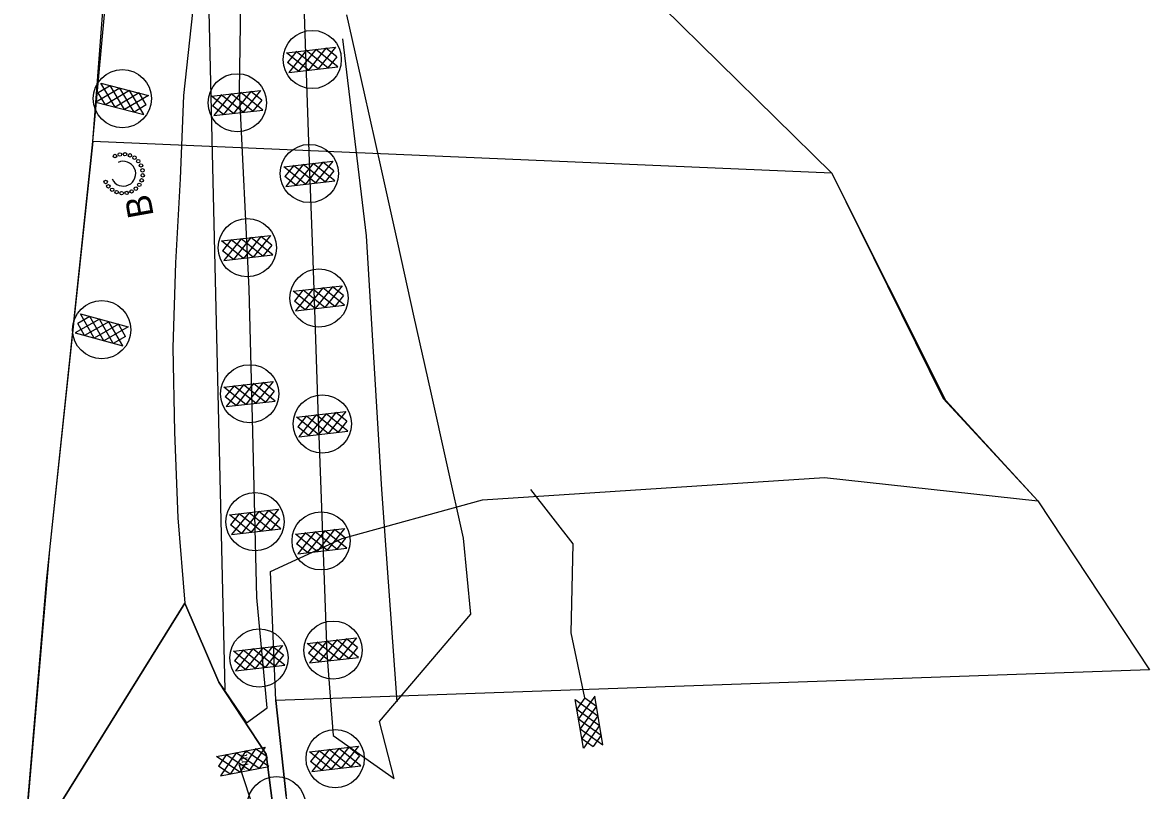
# Model space of a CAD drawing. Extents: x 400935 to 481562, y 415700 to 505362.
# Drawn here: x 474468 to 475127, y 503837 to 504287 of the extents above; entities that cross this region are included whole.
import ezdxf

# ---------------------------------------------------------------- set-up
doc = ezdxf.new("R2010")
doc.units = 0
for name, color, linetype in [('Excelsior Wattle Line Style Final', 7, 'Continuous'), ('Label B CG CELL', 7, 'Continuous'), ('Matting on Slope Note Final CELL', 7, 'Continuous'), ('Old_Level_2', 7, 'Continuous'), ('Rock Pipe Inlet Sediment Trap Type B CG CELL', 7, 'Continuous'), ('Rock Silt Check Type A Both CELL', 7, 'Continuous'), ('Rock Silt Check Type A with Matting and PAM CG CELL', 7, 'Continuous'), ('Rock Silt Check Type A with Matting and PAM Final CELL', 7, 'Continuous'), ('Scratch_Level_3', 7, 'Continuous'), ('Scratch_Level_4', 7, 'Continuous'), ('Temporary Silt Fence Both', 7, 'Continuous')]:
    doc.layers.add(name, color=color, linetype=linetype)

msp = doc.modelspace()

# ---------------------------------------------------------------- linework, layer by layer
at = {"layer": 'Excelsior Wattle Line Style Final'}
msp.add_line((474585.99, 503896.08), (474576.05, 504322.62), dxfattribs=at)
msp.add_lwpolyline([(474686.79, 503889.03), (474677.68, 504013.42), (474668.88, 504161.85), (474654.91, 504277.09), (474654.91, 504277.09)], dxfattribs=at)
at = {"layer": 'Matting on Slope Note Final CELL'}
for p, q in [((474566.88, 504292.53), (474561.67, 504243.99)), ((474667.4, 504246.2), (474657.37, 504291.29)), ((474677.28, 504201.74), (474667.4, 504246.2)), ((474561.67, 504243.99), (474559.66, 504195.21)), ((474687.06, 504157.79), (474677.28, 504201.74)), ((474559.66, 504195.21), (474557.11, 504146.05)), ((474696.75, 504114.22), (474687.06, 504157.79)), ((474557.11, 504146.05), (474555.48, 504096.51)), ((474706.38, 504070.94), (474696.75, 504114.22)), ((474555.48, 504096.51), (474556.49, 504046.86)), ((474715.96, 504027.84), (474706.38, 504070.94)), ((474556.49, 504046.86), (474558.32, 503996.88)), ((474725.53, 503984.81), (474715.96, 504027.84)), ((474558.32, 503996.88), (474562.43, 503946.88)), ((474729.84, 503940.34), (474725.53, 503984.81)), ((474562.43, 503946.88), (474582.45, 503900.64)), ((474676.32, 503877.58), (474729.84, 503940.34)), ((474582.45, 503900.64), (474598.56, 503876.71)), ((474684.93, 503844.28), (474676.32, 503877.58))]:
    msp.add_line(p, q, dxfattribs=at)
for points in [[(474598.56, 503876.71), (474610.64, 503885.55), (474604.64, 503950.12), (474602.2, 504047.14), (474600.1, 504130.89), (474594.49, 504246.69), (474595.54, 504324.66), (474597.97, 504383.09), (474599.37, 504430.72), (474607.08, 504475.48), (474609.67, 504494.69), (474611.07, 504546.92), (474616.75, 504589.94)], [(474686.28, 504550.27), (474667.85, 504549.83), (474651.57, 504492.73), (474646.89, 504443.04), (474642.05, 504389.56), (474642.05, 504389.56), (474631.32, 504337.88), (474632.23, 504291.63), (474633.85, 504245.5), (474635.48, 504199.42), (474637.11, 504153.27), (474638.75, 504106.95), (474640.4, 504060.34), (474642.06, 504013.33), (474643.74, 503965.79), (474645.55, 503917.63), (474649.31, 503869.29), (474684.93, 503844.28)]]:
    msp.add_lwpolyline(points, dxfattribs=at)
at = {"layer": 'Old_Level_2'}
for p, q in [((474581.1, 503857.05), (474609.46, 503862.6)), ((474609.46, 503862.6), (474600.34, 503849.05)), ((474594.65, 503847.93), (474581.1, 503857.05)), ((474586.7, 503858.1), (474582.19, 503851.41)), ((474592.43, 503859.27), (474583.31, 503845.72)), ((474600.34, 503849.05), (474586.74, 503858.15)), ((474598.12, 503860.38), (474588.96, 503846.82)), ((474605.98, 503850.15), (474592.43, 503859.27)), ((474603.76, 503861.5), (474594.65, 503847.93)), ((474611.68, 503851.26), (474598.12, 503860.38)), ((474610.58, 503856.96), (474603.76, 503861.5)), ((474610.58, 503856.96), (474605.98, 503850.15)), ((474588.96, 503846.82), (474582.19, 503851.41)), ((474583.31, 503845.72), (474611.68, 503851.26))]:
    msp.add_line(p, q, dxfattribs=at)
at = {"layer": 'Rock Pipe Inlet Sediment Trap Type B CG CELL'}
for centre in [(474521.61, 504208.55), (474524.45, 504209.45), (474527.43, 504209.59), (474530.35, 504208.95), (474532.99, 504207.58), (474535.2, 504205.57), (474536.8, 504203.05), (474537.71, 504200.21), (474516.12, 504193.36), (474535.83, 504191.67), (474537.2, 504194.32), (474537.84, 504197.23), (474517.72, 504190.84), (474519.93, 504188.83), (474522.57, 504187.46), (474525.49, 504186.82), (474528.47, 504186.96), (474531.31, 504187.86), (474533.82, 504189.47)]:
    msp.add_circle(centre, 1.01, dxfattribs=at)
msp.add_arc((474526.46, 504198.2), 7.26, 205.11854, 115.10973, dxfattribs=at)
at = {"layer": 'Rock Silt Check Type A Both CELL'}
for p, q in [((474795.69, 503861.95), (474790.95, 503890.46)), ((474790.95, 503890.46), (474804.23, 503880.97)), ((474796.62, 503891.42), (474791.89, 503884.74)), ((474802.34, 503892.36), (474792.84, 503879.07)), ((474796.62, 503891.42), (474803.29, 503886.64)), ((474807.08, 503863.85), (474802.34, 503892.36)), ((474791.89, 503884.74), (474805.19, 503875.24)), ((474803.29, 503886.64), (474793.79, 503873.35)), ((474792.84, 503879.07), (474806.14, 503869.52)), ((474804.23, 503880.97), (474794.75, 503867.63)), ((474793.79, 503873.35), (474807.08, 503863.85)), ((474805.19, 503875.24), (474795.69, 503861.95)), ((474806.14, 503869.52), (474801.36, 503862.89)), ((474794.8, 503867.59), (474801.36, 503862.89))]:
    msp.add_line(p, q, dxfattribs=at)
at = {"layer": 'Rock Silt Check Type A with Matting and PAM CG CELL'}
for p, q in [((474524.46, 504248.35), (474510.42, 504240.01)), ((474518.78, 504249.74), (474511.84, 504245.63)), ((474515.99, 504238.59), (474511.84, 504245.63)), ((474513.27, 504251.2), (474541.27, 504244.06)), ((474521.61, 504237.15), (474513.27, 504251.2)), ((474530.08, 504246.91), (474515.99, 504238.59)), ((474527.23, 504235.72), (474518.84, 504249.78)), ((474535.66, 504245.51), (474521.61, 504237.15)), ((474532.8, 504234.3), (474524.46, 504248.35)), ((474538.42, 504232.87), (474530.08, 504246.91)), ((474539.86, 504238.49), (474535.66, 504245.51)), ((474510.42, 504240.01), (474538.42, 504232.87)), ((474541.27, 504244.06), (474527.23, 504235.72)), ((474539.86, 504238.49), (474532.8, 504234.3)), ((474512.49, 504113.1), (474498.29, 504105.03)), ((474506.83, 504114.61), (474499.81, 504110.62)), ((474501.35, 504116.16), (474529.22, 504108.5)), ((474509.43, 504101.97), (474501.35, 504116.16)), ((474515.02, 504100.43), (474506.89, 504114.64)), ((474520.56, 504098.9), (474512.49, 504113.1)), ((474503.83, 504103.5), (474499.81, 504110.62)), ((474518.08, 504111.57), (474503.83, 504103.5)), ((474523.63, 504110.05), (474509.43, 504101.97)), ((474529.22, 504108.5), (474515.02, 504100.43)), ((474526.15, 504097.37), (474518.08, 504111.57)), ((474527.7, 504102.96), (474523.63, 504110.05)), ((474498.29, 504105.03), (474526.15, 504097.37)), ((474527.7, 504102.96), (474520.56, 504098.9))]:
    msp.add_line(p, q, dxfattribs=at)
for centre in [(474525.92, 504242.15), (474513.83, 504106.88)]:
    msp.add_circle(centre, 17.04, dxfattribs=at)
at = {"layer": 'Rock Silt Check Type A with Matting and PAM Final CELL'}
for p, q in [((474621.96, 504269.02), (474650.67, 504272.32)), ((474644.91, 504271.67), (474634.76, 504258.86)), ((474650.67, 504272.32), (474640.52, 504259.53)), ((474651.34, 504266.61), (474644.91, 504271.67)), ((474634.76, 504258.86), (474621.96, 504269.02)), ((474627.63, 504269.62), (474622.61, 504263.31)), ((474633.44, 504270.34), (474623.28, 504257.54)), ((474640.52, 504259.53), (474627.68, 504269.68)), ((474639.2, 504271), (474628.99, 504258.2)), ((474646.23, 504260.18), (474633.44, 504270.34)), ((474651.99, 504260.84), (474639.2, 504271)), ((474651.34, 504266.61), (474646.23, 504260.18)), ((474628.99, 504258.2), (474622.61, 504263.31)), ((474623.28, 504257.54), (474651.99, 504260.84)), ((474578.1, 504243.67), (474606.81, 504246.97)), ((474589.57, 504244.99), (474579.41, 504232.19)), ((474595.33, 504245.65), (474585.13, 504232.85)), ((474602.36, 504234.83), (474589.57, 504244.99)), ((474601.04, 504246.32), (474590.89, 504233.51)), ((474608.12, 504235.49), (474595.33, 504245.65)), ((474606.81, 504246.97), (474596.65, 504234.17)), ((474607.47, 504241.26), (474601.04, 504246.32)), ((474590.89, 504233.51), (474578.1, 504243.67)), ((474583.76, 504244.27), (474578.74, 504237.95)), ((474596.65, 504234.17), (474583.81, 504244.32)), ((474607.47, 504241.26), (474602.36, 504234.83)), ((474585.13, 504232.85), (474578.74, 504237.95)), ((474579.41, 504232.19), (474608.12, 504235.49)), ((474620.32, 504202.29), (474649.03, 504205.59)), ((474649.03, 504205.59), (474638.88, 504192.79)), ((474633.12, 504192.13), (474620.32, 504202.29)), ((474625.99, 504202.89), (474620.97, 504196.57)), ((474631.8, 504203.61), (474621.64, 504190.81)), ((474638.88, 504192.79), (474626.04, 504202.94)), ((474637.56, 504204.27), (474627.35, 504191.47)), ((474644.59, 504193.45), (474631.8, 504203.61)), ((474643.27, 504204.94), (474633.12, 504192.13)), ((474650.35, 504194.11), (474637.56, 504204.27)), ((474649.7, 504199.88), (474643.27, 504204.94)), ((474649.7, 504199.88), (474644.59, 504193.45)), ((474627.35, 504191.47), (474620.97, 504196.57)), ((474621.64, 504190.81), (474650.35, 504194.11)), ((474583.94, 504158.83), (474612.65, 504162.13)), ((474589.61, 504159.43), (474584.58, 504153.12)), ((474595.42, 504160.15), (474585.26, 504147.35)), ((474602.5, 504149.33), (474589.65, 504159.49)), ((474601.18, 504160.81), (474590.97, 504148.01)), ((474608.21, 504149.99), (474595.42, 504160.15)), ((474606.89, 504161.48), (474596.73, 504148.67)), ((474613.97, 504150.65), (474601.18, 504160.81)), ((474612.65, 504162.13), (474602.5, 504149.33)), ((474613.32, 504156.42), (474606.89, 504161.48)), ((474596.73, 504148.67), (474583.94, 504158.83)), ((474590.97, 504148.01), (474584.58, 504153.12)), ((474613.32, 504156.42), (474608.21, 504149.99)), ((474585.26, 504147.35), (474613.97, 504150.65)), ((474625.92, 504129.38), (474654.63, 504132.68)), ((474638.72, 504119.22), (474625.92, 504129.38)), ((474631.59, 504129.98), (474626.57, 504123.67)), ((474637.4, 504130.7), (474627.24, 504117.91)), ((474644.48, 504119.89), (474631.64, 504130.04)), ((474643.16, 504131.36), (474632.95, 504118.56)), ((474650.19, 504120.54), (474637.4, 504130.7)), ((474648.87, 504132.03), (474638.72, 504119.22)), ((474655.95, 504121.2), (474643.16, 504131.36)), ((474654.63, 504132.68), (474644.48, 504119.89)), ((474655.3, 504126.97), (474648.87, 504132.03)), ((474655.3, 504126.97), (474650.19, 504120.54)), ((474632.95, 504118.56), (474626.57, 504123.67)), ((474627.24, 504117.91), (474655.95, 504121.2)), ((474585.39, 504073.35), (474614.1, 504076.64)), ((474591.06, 504073.95), (474586.04, 504067.63)), ((474596.87, 504074.66), (474586.71, 504061.87)), ((474603.95, 504063.85), (474591.11, 504074)), ((474602.63, 504075.33), (474592.42, 504062.53)), ((474609.66, 504064.51), (474596.87, 504074.66)), ((474608.34, 504075.99), (474598.19, 504063.19)), ((474615.42, 504065.17), (474602.63, 504075.33)), ((474614.1, 504076.64), (474603.95, 504063.85)), ((474614.77, 504070.93), (474608.34, 504075.99)), ((474598.19, 504063.19), (474585.39, 504073.35)), ((474592.42, 504062.53), (474586.04, 504067.63)), ((474614.77, 504070.93), (474609.66, 504064.51)), ((474586.71, 504061.87), (474615.42, 504065.17)), ((474627.89, 504055.72), (474656.6, 504059.02)), ((474640.68, 504045.56), (474627.89, 504055.72)), ((474633.55, 504056.32), (474628.53, 504050.01)), ((474639.36, 504057.04), (474629.2, 504044.25)), ((474646.44, 504046.23), (474633.6, 504056.38)), ((474645.12, 504057.7), (474634.92, 504044.9)), ((474652.15, 504046.88), (474639.36, 504057.04)), ((474650.83, 504058.37), (474640.68, 504045.56)), ((474657.92, 504047.55), (474645.12, 504057.7)), ((474656.6, 504059.02), (474646.44, 504046.23)), ((474657.27, 504053.31), (474650.83, 504058.37)), ((474634.92, 504044.9), (474628.53, 504050.01)), ((474629.2, 504044.25), (474657.92, 504047.55)), ((474657.27, 504053.31), (474652.15, 504046.88)), ((474588.56, 503998.48), (474617.27, 504001.77)), ((474611.51, 504001.12), (474601.36, 503988.32)), ((474617.27, 504001.77), (474607.12, 503988.98)), ((474617.94, 503996.06), (474611.51, 504001.12)), ((474601.36, 503988.32), (474588.56, 503998.48)), ((474594.23, 503999.08), (474589.21, 503992.76)), ((474600.04, 503999.79), (474589.88, 503987)), ((474607.12, 503988.98), (474594.27, 503999.13)), ((474605.8, 504000.46), (474595.59, 503987.66)), ((474612.83, 503989.64), (474600.04, 503999.79)), ((474618.59, 503990.3), (474605.8, 504000.46)), ((474617.94, 503996.06), (474612.83, 503989.64)), ((474595.59, 503987.66), (474589.21, 503992.76)), ((474589.88, 503987), (474618.59, 503990.3)), ((474627.19, 503987.26), (474655.91, 503990.56)), ((474632.86, 503987.87), (474627.84, 503981.55)), ((474638.67, 503988.58), (474628.51, 503975.79)), ((474645.75, 503977.77), (474632.91, 503987.92)), ((474644.43, 503989.24), (474634.23, 503976.45)), ((474651.46, 503978.43), (474638.67, 503988.58)), ((474650.14, 503989.91), (474639.99, 503977.11)), ((474657.22, 503979.09), (474644.43, 503989.24)), ((474655.91, 503990.56), (474645.75, 503977.77)), ((474656.57, 503984.85), (474650.14, 503989.91)), ((474639.99, 503977.11), (474627.19, 503987.26)), ((474634.23, 503976.45), (474627.84, 503981.55)), ((474656.57, 503984.85), (474651.46, 503978.43)), ((474628.51, 503975.79), (474657.22, 503979.09)), ((474590.87, 503918.74), (474619.58, 503922.04)), ((474619.58, 503922.04), (474609.42, 503909.24)), ((474634.15, 503923.31), (474662.86, 503926.61)), ((474646.94, 503913.15), (474634.15, 503923.31)), ((474639.82, 503923.91), (474634.79, 503917.6)), ((474645.62, 503924.63), (474635.47, 503911.83)), ((474652.71, 503913.82), (474639.86, 503923.97)), ((474651.39, 503925.29), (474641.18, 503912.49)), ((474658.42, 503914.47), (474645.62, 503924.63)), ((474657.1, 503925.96), (474646.94, 503913.15)), ((474664.18, 503915.13), (474651.39, 503925.29)), ((474662.86, 503926.61), (474652.71, 503913.82)), ((474663.53, 503920.9), (474657.1, 503925.96)), ((474603.66, 503908.58), (474590.87, 503918.74)), ((474596.54, 503919.34), (474591.51, 503913.03)), ((474602.34, 503920.06), (474592.19, 503907.26)), ((474609.42, 503909.24), (474596.58, 503919.4)), ((474608.11, 503920.72), (474597.9, 503907.92)), ((474615.14, 503909.9), (474602.34, 503920.06)), ((474613.82, 503921.39), (474603.66, 503908.58)), ((474620.9, 503910.56), (474608.11, 503920.72)), ((474620.25, 503916.33), (474613.82, 503921.39)), ((474620.25, 503916.33), (474615.14, 503909.9)), ((474641.18, 503912.49), (474634.79, 503917.6)), ((474663.53, 503920.9), (474658.42, 503914.47)), ((474597.9, 503907.92), (474591.51, 503913.03)), ((474592.19, 503907.26), (474620.9, 503910.56)), ((474635.47, 503911.83), (474664.18, 503915.13)), ((474635.4, 503859.82), (474664.12, 503863.12)), ((474658.35, 503862.47), (474648.2, 503849.66)), ((474664.12, 503863.12), (474653.96, 503850.33)), ((474664.78, 503857.41), (474658.35, 503862.47)), ((474648.2, 503849.66), (474635.4, 503859.82)), ((474641.07, 503860.42), (474636.05, 503854.11)), ((474646.88, 503861.14), (474636.72, 503848.34)), ((474653.96, 503850.33), (474641.12, 503860.48)), ((474652.64, 503861.8), (474642.44, 503849)), ((474659.67, 503850.98), (474646.88, 503861.14)), ((474665.43, 503851.64), (474652.64, 503861.8)), ((474664.78, 503857.41), (474659.67, 503850.98)), ((474642.44, 503849), (474636.05, 503854.11)), ((474636.72, 503848.34), (474665.43, 503851.64))]:
    msp.add_line(p, q, dxfattribs=at)
for centre in [(474637.01, 504265.06), (474593.14, 504239.71), (474635.37, 504198.33), (474598.98, 504154.87), (474640.97, 504125.42), (474600.44, 504069.39), (474642.93, 504051.76), (474603.6, 503994.52), (474642.24, 503983.31), (474649.19, 503919.35), (474605.91, 503914.78), (474650.45, 503855.86), (474616.11, 503828.35)]:
    msp.add_circle(centre, 17.04, dxfattribs=at)
at = {"layer": 'Scratch_Level_3'}
msp.add_lwpolyline([(474626.67, 503758.55), (474609.66, 503805.2), (474594.28, 503852.41)], dxfattribs=at)
at = {"layer": 'Scratch_Level_4'}
msp.add_lwpolyline([(474622.89, 503758.26), (474610.09, 503858.5), (474582.45, 503900.64), (474562.43, 503946.88), (474467.5, 503793.86), (474481.43, 503959.46), (474508.73, 504217.08), (474525.69, 504438.48), (474522.41, 504527.71), (474521.7, 504585.06), (474546.76, 504585.2), (474546.76, 504585.2), (474546.76, 504585.2), (474546.76, 504585.2), (474546.76, 504585.2), (474638.46, 504565.86), (474728.78, 504417.22), (474842.23, 504295.6), (474941.08, 504198.57), (475006.21, 504066.62), (475061.71, 504006.75), (475126.97, 503907.83), (474615.72, 503889.9), (474621.71, 503834.05)], dxfattribs=at)
for points in [[(474508.73, 504217.08), (474520.65, 504348.92), (474525.46, 504402.14), (474525.69, 504438.48), (474728.78, 504417.22), (474842.23, 504295.6), (474941.08, 504198.57)], [(474508.73, 504217.08), (474483.24, 503977.98), (474467.5, 503793.86), (474562.43, 503946.88), (474582.45, 503900.64), (474610.09, 503858.5), (474622.89, 503758.26), (474637.16, 503760.09), (474621.71, 503834.05), (474615.72, 503889.9), (474612.56, 503965.37), (474654.57, 503984.63), (474736.73, 504007.41), (474936.71, 504020.39), (475061.71, 504006.75), (475007.9, 504065.5), (474941.08, 504198.57)]]:
    msp.add_lwpolyline(points, close=True, dxfattribs=at)
at = {"layer": 'Temporary Silt Fence Both'}
msp.add_lwpolyline([(474796.62, 503891.42), (474796.62, 503891.42), (474788.52, 503929.56), (474789.73, 503981.48), (474765.02, 504013.35)], dxfattribs=at)

# ---------------------------------------------------------------- texts
at = {"layer": 'Label B CG CELL'}
msp.add_text('B', height=15, rotation=100.25385, dxfattribs=at).set_placement((474544.33, 504173.72))
at = {"layer": 'Old_Level_2'}
msp.add_text('*Int.', height=4.746, rotation=96.55384, dxfattribs=at).set_placement((474599.96, 503849.27))

doc.saveas('drawing.dxf')
